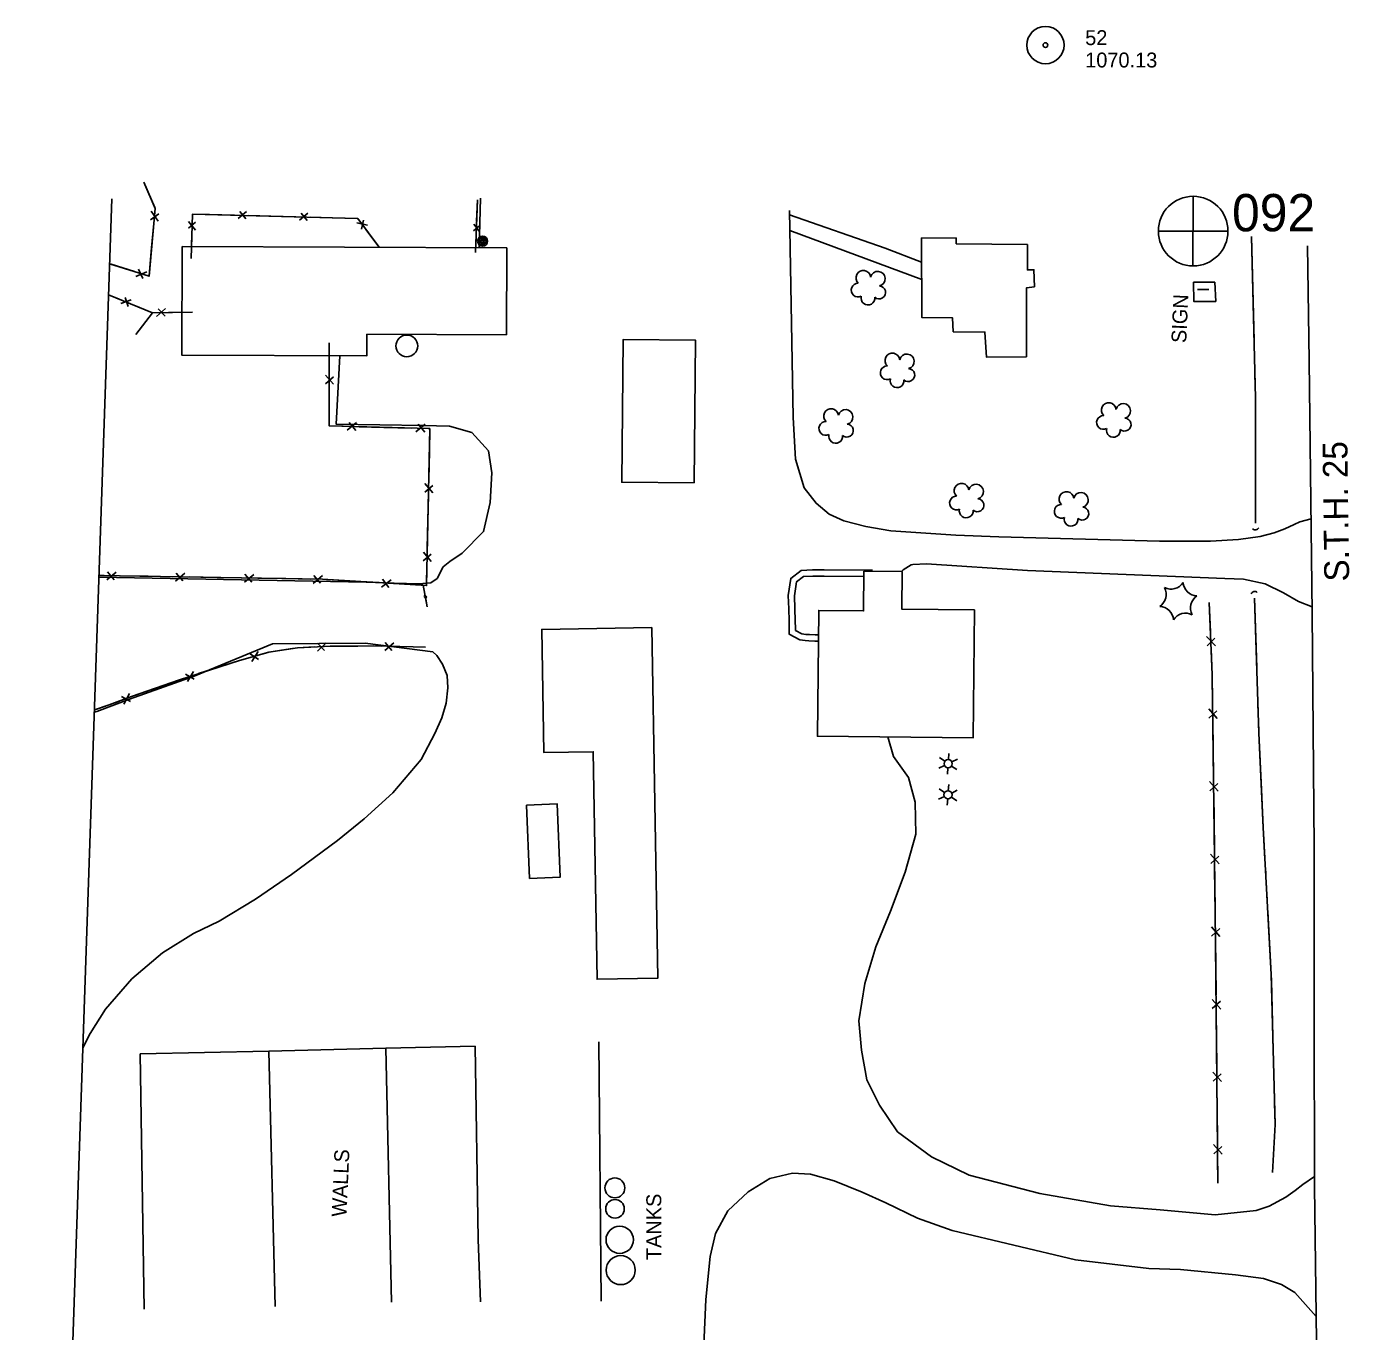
# Model space of a CAD drawing. Extents: x 296471 to 298892, y 33801 to 34997.
# Drawn here: x 297188 to 297720, y 34456 to 34981 of the extents above; entities that cross this region are included whole.
import ezdxf

# ---------------------------------------------------------------- set-up
doc = ezdxf.new("R2010")
doc.units = 0
for name, color, linetype in [('Level 11', 7, 'Continuous'), ('Level 12', 7, 'Continuous'), ('Level 14', 7, 'Continuous'), ('Level 15', 7, 'Continuous'), ('Level 17', 7, 'Continuous'), ('Level 18', 7, 'Continuous'), ('Level 19', 7, 'Continuous'), ('Level 4', 7, 'Continuous'), ('Level 6', 7, 'Continuous')]:
    doc.layers.add(name, color=color, linetype=linetype)

msp = doc.modelspace()

# ---------------------------------------------------------------- linework, layer by layer
at = {"layer": 'Level 11'}
msp.add_lwpolyline([(297712.34, 33851.57), (297711.29, 33914.53), (297711.16, 33974.94), (297710.5, 34028.32), (297710.34, 34091.16), (297709.89, 34145.17), (297708.94, 34222.49), (297708.52, 34278.1), (297707.52, 34365.88), (297707.09, 34441.48), (297706.15, 34514.1), (297705.99, 34583.52), (297706.04, 34650.6), (297705.21, 34744.77), (297704.07, 34846.29), (297703.4, 34892.56)], dxfattribs=at)
at = {"layer": 'Level 12'}
for points in [[(297380.91, 34856.8), (297381.05, 34891.74), (297250.46, 34892.28), (297250.28, 34848.61), (297324.72, 34848.3), (297324.76, 34857.03)], [(297456.56, 34797.17), (297427.36, 34797.44), (297427.89, 34854.88), (297457.09, 34854.61)], [(297569.36, 34746.06), (297568.79, 34694.57), (297506.1, 34695.28), (297506.67, 34745.9), (297524.67, 34745.7), (297524.85, 34761.67), (297540.2, 34761.5), (297540.03, 34746.39)], [(297439.45, 34738.98), (297395.18, 34738.23), (297396.02, 34688.7), (297415.9, 34689.03), (297417.45, 34597.46), (297441.84, 34597.88)], [(297389.02, 34667.51), (297401.39, 34668.02), (297402.59, 34638.56), (297390.23, 34638.05)]]:
    msp.add_lwpolyline(points, close=True, dxfattribs=at)
msp.add_lwpolyline([(297590.68, 34893.06), (297590.64, 34882.87), (297593.27, 34882.97), (297593.44, 34876.13), (297590.25, 34875.67), (297590.24, 34847.96), (297574.17, 34847.76), (297573.54, 34857.91), (297560.75, 34858), (297560.43, 34863.64), (297548.16, 34863.74), (297547.97, 34895.74), (297561.93, 34895.77), (297562.01, 34893.43), (297590.68, 34893.06)], dxfattribs=at)
for centre, radius in [((297340.83, 34852.31), 4.39), ((297424.59, 34513.52), 4), ((297424.64, 34505.1), 3.74), ((297426.52, 34492.66), 5.5), ((297426.94, 34480.44), 5.85)]:
    msp.add_circle(centre, radius, dxfattribs=at)
at = {"layer": 'Level 14'}
for p, q in [((297659.15, 34874.96), (297663.59, 34875.01)), ((297558.84, 34685.85), (297559.01, 34688.37)), ((297557.28, 34683.48), (297554.92, 34682.38)), ((297557.36, 34685.18), (297555.19, 34686.64)), ((297560.12, 34683.28), (297562.25, 34681.82)), ((297560.24, 34684.91), (297562.47, 34686.06)), ((297558.6, 34682.58), (297558.42, 34679.99)), ((297557.3, 34672.67), (297555.13, 34674.13)), ((297558.78, 34673.34), (297558.96, 34675.86)), ((297560.18, 34672.4), (297562.41, 34673.55)), ((297557.22, 34670.97), (297554.87, 34669.87)), ((297558.54, 34670.07), (297558.36, 34667.48)), ((297560.07, 34670.77), (297562.2, 34669.31))]:
    msp.add_line(p, q, dxfattribs=at)
for centre, radius in [((297371.36, 34894.47), 2.02), ((297371.34, 34894.47), 1.52), ((297371.38, 34894.48), 1.01), ((297371.37, 34894.48), 0.502), ((297558.74, 34684.21), 1.64), ((297558.68, 34671.7), 1.64)]:
    msp.add_circle(centre, radius, dxfattribs=at)
at = {"layer": 'Level 15'}
for p, q in [((297237.64, 34902.99), (297241, 34905.46)), ((297240.81, 34902.54), (297237.95, 34906.48)), ((297255.85, 34902.1), (297252.95, 34899.72)), ((297252.98, 34902.35), (297255.73, 34898.95)), ((297276.29, 34906.36), (297272.91, 34903.57)), ((297276.06, 34903.49), (297273.65, 34906.37)), ((297300.99, 34905.7), (297297.62, 34902.92)), ((297300.77, 34902.83), (297298.36, 34905.71)), ((297325.04, 34900.86), (297320.77, 34901.81)), ((297322.64, 34899.28), (297323.43, 34902.94)), ((297370.13, 34898.36), (297367.77, 34901.27)), ((297367.67, 34898.58), (297370.16, 34900.61)), ((297231.79, 34880.23), (297236.26, 34882.15)), ((297232.92, 34883.22), (297234.6, 34879.4)), ((297229.9, 34870.84), (297225.74, 34869.44)), ((297228.66, 34868.24), (297227.44, 34871.79)), ((297243.71, 34867.42), (297240.14, 34864.19)), ((297243.6, 34864.26), (297240.82, 34867.3)), ((297311.36, 34836.87), (297308.14, 34840.55)), ((297308.14, 34837.03), (297311.29, 34839.81)), ((297320.62, 34821.55), (297316.85, 34818.42)), ((297320.37, 34818.33), (297317.67, 34821.56)), ((297348.29, 34820.84), (297344.52, 34817.72)), ((297348.04, 34817.63), (297345.35, 34820.85)), ((297348.08, 34793.46), (297351.29, 34796.17)), ((297351.29, 34793.22), (297348.16, 34796.98)), ((297347.49, 34765.78), (297350.7, 34768.49)), ((297350.71, 34765.54), (297347.57, 34769.31)), ((297220.11, 34758.18), (297223.86, 34761.34)), ((297220.33, 34761.4), (297223.06, 34758.2)), ((297247.79, 34757.71), (297251.54, 34760.87)), ((297248.01, 34760.93), (297250.74, 34757.73)), ((297275.47, 34757.24), (297279.21, 34760.4)), ((297275.69, 34760.46), (297278.41, 34757.26)), ((297303.14, 34756.77), (297306.89, 34759.93)), ((297303.37, 34759.99), (297306.09, 34756.79)), ((297330.71, 34755.26), (297334.59, 34758.25)), ((297331.07, 34758.47), (297333.65, 34755.15)), ((297348.93, 34750.91), (297347.71, 34751.87)), ((297347.92, 34750.77), (297348.74, 34751.82)), ((297304.84, 34729.53), (297308.33, 34732.86)), ((297304.86, 34732.7), (297307.74, 34729.73)), ((297331.95, 34729.78), (297335.65, 34732.87)), ((297332.18, 34732.94), (297334.85, 34729.79)), ((297666.32, 34731.64), (297662.76, 34735.39)), ((297662.92, 34731.67), (297666.12, 34734.74)), ((297277.74, 34728.46), (297281.2, 34726.2)), ((297278.42, 34725.36), (297281.08, 34729.38)), ((297251.71, 34720.29), (297255.25, 34718.18)), ((297252.52, 34717.23), (297255.01, 34721.36)), ((297225.96, 34711.24), (297229.6, 34709.28)), ((297226.91, 34708.21), (297229.21, 34712.44)), ((297667.04, 34702.38), (297663.59, 34706.23)), ((297663.64, 34702.51), (297666.93, 34705.49)), ((297667.42, 34673.16), (297663.97, 34677.01)), ((297664.02, 34673.29), (297667.3, 34676.27)), ((297667.8, 34643.94), (297664.35, 34647.79)), ((297664.4, 34644.07), (297667.68, 34647.05)), ((297668.14, 34614.72), (297664.71, 34618.58)), ((297664.74, 34614.86), (297668.04, 34617.83)), ((297668.43, 34585.5), (297665, 34589.36)), ((297665.04, 34585.64), (297668.33, 34588.61)), ((297668.72, 34556.28), (297665.29, 34560.14)), ((297665.33, 34556.42), (297668.62, 34559.39)), ((297669.01, 34527.06), (297665.58, 34530.93)), ((297665.61, 34527.21), (297668.91, 34530.17))]:
    msp.add_line(p, q, dxfattribs=at)
for points in [[(297221.24, 34885.41), (297237.11, 34880.33), (297239.54, 34907.63), (297234.96, 34918.25)], [(297239.38, 34907.99), (297234.96, 34918.25)], [(297368.5, 34889.95), (297369.28, 34911.14)], [(297368.96, 34902.53), (297369.28, 34911.14)], [(297238.12, 34891.77), (297239, 34901.55)], [(297329.66, 34892.01), (297321.08, 34903.63), (297254.64, 34905.39), (297253.99, 34887.46)], [(297261.4, 34905.21), (297254.64, 34905.39), (297254.56, 34903.33)], [(297271.44, 34904.94), (297261.4, 34905.21)], [(297286.1, 34904.56), (297277.27, 34904.79)], [(297296.14, 34904.29), (297286.1, 34904.56)], [(297310.81, 34903.9), (297301.98, 34904.13)], [(297320.85, 34903.63), (297310.81, 34903.9)], [(297254.35, 34897.49), (297254.16, 34892.26)], [(297329.66, 34892.01), (297324.41, 34899.12)], [(297368.56, 34891.79), (297368.78, 34897.52)], [(297237.13, 34880.65), (297238.12, 34891.77)], [(297221.24, 34885.41), (297221.87, 34885.21)], [(297221.87, 34885.21), (297231.22, 34882.21)], [(297666.53, 34870.15), (297666.04, 34877.95), (297657.52, 34877.91)], [(297657.52, 34877.91), (297657.58, 34870.22), (297666.53, 34870.15)], [(297238.45, 34865.63), (297220.82, 34872.93)], [(297224.85, 34871.26), (297220.82, 34872.93)], [(297238.45, 34865.63), (297230.26, 34869.02)], [(297254.58, 34865.91), (297238.45, 34865.63), (297231.73, 34856.86)], [(297238.45, 34865.63), (297238.45, 34865.63), (297231.73, 34856.86)], [(297250.35, 34865.84), (297244.87, 34865.74)], [(297216.97, 34759.96), (297306.9, 34758.44), (297348.78, 34755.9), (297350.11, 34819.07), (297309.66, 34820.1), (297309.6, 34853.5)], [(297309.62, 34842.25), (297309.61, 34848.37)], [(297309.65, 34825.82), (297309.64, 34835.71)], [(297315.19, 34819.96), (297309.66, 34820.1), (297309.65, 34825.82)], [(297331.62, 34819.54), (297321.73, 34819.79)], [(297342.86, 34819.25), (297331.62, 34819.54)], [(297349.92, 34809.89), (297350.11, 34819.07), (297349.4, 34819.09)], [(297349.68, 34798.64), (297349.92, 34809.89)], [(297349.33, 34782.21), (297349.54, 34792.11)], [(297349.1, 34770.97), (297349.33, 34782.21)], [(297347.42, 34755.98), (297348.78, 34755.9), (297348.96, 34764.43)], [(297216.97, 34759.96), (297218.99, 34759.93)], [(297225.53, 34759.82), (297236.77, 34759.63)], [(297236.77, 34759.63), (297246.66, 34759.46)], [(297253.2, 34759.35), (297264.45, 34759.16)], [(297264.45, 34759.16), (297274.34, 34758.99)], [(297280.88, 34758.88), (297292.13, 34758.69)], [(297292.13, 34758.69), (297302.02, 34758.52)], [(297308.56, 34758.34), (297319.79, 34757.66)], [(297319.79, 34757.66), (297329.66, 34757.06)], [(297336.19, 34756.66), (297347.42, 34755.98)], [(297349.04, 34747.37), (297347.42, 34755.98)], [(297348.08, 34752.48), (297347.42, 34755.98)], [(297349.04, 34747.37), (297348.46, 34750.44)], [(297667.31, 34515.38), (297666.22, 34625.08), (297664.98, 34719.96), (297663.76, 34749.11)], [(297664.26, 34737.24), (297663.76, 34749.11)], [(297215.12, 34705.86), (297221.06, 34707.85), (297230.1, 34711.21), (297249.36, 34718), (297273.53, 34725.77), (297285.36, 34729.04), (297296.91, 34730.87), (297310.23, 34731.48), (297327.43, 34731.57), (297343.43, 34731.25), (297348.34, 34731.05)], [(297293.95, 34730.4), (297296.91, 34730.87), (297303.63, 34731.18)], [(297310.06, 34731.47), (297310.23, 34731.48), (297321.12, 34731.53)], [(297321.12, 34731.53), (297327.43, 34731.57), (297330.85, 34731.5)], [(297337.28, 34731.37), (297343.43, 34731.25), (297348.34, 34731.05)], [(297267.57, 34723.86), (297273.53, 34725.77), (297276.88, 34726.7)], [(297283.08, 34728.41), (297285.36, 34729.04), (297293.95, 34730.4)], [(297664.99, 34719.91), (297664.98, 34719.96), (297664.55, 34730.34)], [(297257.04, 34720.47), (297267.57, 34723.86)], [(297231.29, 34711.63), (297241.73, 34715.31)], [(297241.73, 34715.31), (297249.36, 34718), (297250.92, 34718.5)], [(297665.14, 34708.04), (297664.99, 34719.91)], [(297215.12, 34705.86), (297216.08, 34706.18)], [(297216.08, 34706.18), (297221.06, 34707.85), (297225.26, 34709.41)], [(297665.36, 34690.69), (297665.23, 34701.14)], [(297665.52, 34678.82), (297665.36, 34690.69)], [(297665.74, 34661.47), (297665.61, 34671.92)], [(297665.9, 34649.6), (297665.74, 34661.47)], [(297666.12, 34632.26), (297665.99, 34642.7)], [(297666.26, 34620.39), (297666.22, 34625.08), (297666.12, 34632.26)], [(297666.44, 34603.04), (297666.33, 34613.48)], [(297666.55, 34591.17), (297666.44, 34603.04)], [(297666.73, 34573.82), (297666.62, 34584.26)], [(297419.04, 34467.97), (297418.07, 34572.33)], [(297666.84, 34561.95), (297666.73, 34573.82)], [(297233.47, 34567.44), (297285.28, 34568.57), (297332.4, 34569.7), (297368.31, 34570.5)], [(297235.14, 34464.73), (297233.47, 34567.44)], [(297287.84, 34465.82), (297285.28, 34568.57)], [(297334.71, 34467.52), (297332.4, 34569.7)], [(297370.55, 34467.67), (297369.57, 34492.82), (297368.31, 34570.5)], [(297667.02, 34544.6), (297666.91, 34555.04)], [(297667.13, 34532.73), (297667.02, 34544.6)], [(297667.31, 34515.38), (297667.2, 34525.83)]]:
    msp.add_lwpolyline(points, dxfattribs=at)
for centre, radius, start, end in [((297682.37, 34779.88), 1.59, 224.6912, 330.9308), ((297682.13, 34751.9), 1.58, 49.445, 155.6846)]:
    msp.add_arc(centre, radius, start, end, dxfattribs=at)
at = {"layer": 'Level 17'}
for points in [[(297369.9, 34891.78), (297370.57, 34911.79)], [(297494.89, 34906.82), (297496.39, 34823.53), (297497.22, 34806.71), (297500.8, 34795.26), (297505.57, 34789), (297510.81, 34784.58), (297516.68, 34781.95), (297525.56, 34779.71), (297535.66, 34777.86), (297547.78, 34777.06), (297561.86, 34776.17), (297579.07, 34775.51), (297643.74, 34773.74), (297664.31, 34773.7), (297675.53, 34774.48), (297684.36, 34775.58), (297689.92, 34777.11), (297694.28, 34778.73), (297697.96, 34780.46), (297700.24, 34781.48), (297704.78, 34782.69)], [(297494.92, 34905.04), (297533.36, 34891.65), (297548.03, 34886.02)], [(297495.04, 34898.75), (297548.07, 34879)], [(297216.95, 34759.29), (297324.48, 34757.22), (297335.73, 34756.82), (297345.7, 34756.61), (297350.5, 34757.04), (297353.11, 34758.73), (297355.53, 34763.4), (297358.2, 34765.58), (297363.06, 34768.9), (297371.76, 34777.62), (297374.35, 34789.35), (297375.02, 34801.28), (297373.7, 34810.15), (297367.08, 34817.54), (297358.03, 34820.03), (297347.57, 34820.24), (297312.47, 34820.82), (297313.88, 34848.35)], [(297705.18, 34747.35), (297699.68, 34749.49), (297693.75, 34752.99), (297686.33, 34756.53), (297677.54, 34758.41), (297670.11, 34758.68), (297590.63, 34761.99), (297549.95, 34764.6), (297544.55, 34764.42), (297543.83, 34764.26), (297540.63, 34762.24), (297539.91, 34761.5)], [(297528.33, 34762.04), (297508.82, 34762.2), (297504.18, 34762.19), (297499.61, 34762), (297495.37, 34758.76), (297494.37, 34751.92), (297494.56, 34746.5), (297494.7, 34741.7), (297494.79, 34738.38), (297494.8, 34736.31), (297499.01, 34734.09), (297501.15, 34733.78), (297502.7, 34733.65), (297505.09, 34733.53), (297506.53, 34733.53)], [(297524.83, 34759.57), (297508.81, 34759.7), (297504.23, 34759.69), (297500.5, 34759.53), (297497.69, 34757.39), (297496.87, 34751.78), (297497.05, 34746.58), (297497.2, 34741.77), (297497.29, 34738.42), (297497.29, 34737.83), (297499.8, 34736.5), (297501.43, 34736.26), (297502.87, 34736.14), (297505.15, 34736.03), (297506.56, 34736.03)], [(297210.49, 34569.82), (297213.38, 34575.66), (297219.53, 34585.43), (297230.2, 34597.63), (297242.57, 34608.07), (297254.95, 34615.88), (297265.36, 34620.86), (297279.94, 34629.64), (297294.39, 34639.64), (297312.96, 34653.34), (297323.65, 34662), (297335.2, 34672.44), (297346.62, 34685.89), (297352.19, 34696.35), (297354.92, 34702.63), (297356.72, 34708.62), (297357.39, 34714.73), (297357.11, 34719.64), (297355.18, 34724.26), (297352.99, 34727.73), (297351.31, 34729.23), (297324.07, 34732.68), (297286.8, 34732.47), (297255.3, 34719.4), (297229.22, 34710.2), (297216.11, 34705.21), (297215.09, 34704.96)], [(297534.42, 34694.96), (297536.76, 34687.15), (297542.73, 34678.65), (297545.45, 34668.75), (297545.69, 34655.9), (297541.49, 34640.62), (297535.51, 34624.87), (297529.65, 34610.54), (297525.17, 34595.82), (297522.83, 34580.74), (297523.8, 34568.94), (297526, 34557.04), (297531.14, 34546.77), (297538.39, 34536.04), (297552.03, 34526.03), (297567.19, 34518.66), (297595.69, 34511.27), (297624.13, 34506.24), (297644.08, 34504.71), (297666.22, 34502.73), (297682.63, 34504.4), (297687.99, 34506.18), (297694.63, 34509.82), (297698.44, 34512.42), (297701.49, 34514.92), (297706.14, 34518.17)], [(297706.83, 34461.72), (297698.25, 34471.44), (297692.88, 34474.71), (297685.62, 34477.08), (297674.42, 34478.59), (297652.21, 34480.74), (297639.5, 34481.07), (297610.03, 34484.58), (297560.28, 34496.43), (297546.36, 34501.36), (297533.66, 34507.46), (297524.13, 34511.84), (297512.9, 34516.4), (297503.27, 34519.09), (297496.06, 34519.39), (297486.92, 34517.24), (297478.24, 34511.94), (297470.04, 34504.26), (297465.03, 34495.23), (297462.99, 34485.89), (297461.14, 34468.65), (297460.39, 34450.19)]]:
    msp.add_lwpolyline(points, dxfattribs=at)
at = {"layer": 'Level 18'}
for centre, radius, start, end in [((297524.58, 34879.72), 2.97, 5.9397, 227.1736), ((297530.42, 34879.35), 2.97, 283.5905, 166.5638), ((297522.5, 34874.76), 2.78, 88.9106, 296.6836), ((297530.95, 34873.85), 2.61, 228.2958, 86.2284), ((297526.44, 34871.58), 2.78, 165.5876, 6.5987), ((297536.28, 34846.45), 2.97, 5.9397, 227.1736), ((297542.12, 34846.09), 2.97, 283.5905, 166.5638), ((297534.21, 34841.49), 2.78, 88.9106, 296.6836), ((297542.65, 34840.59), 2.61, 228.2958, 86.2284), ((297538.15, 34838.32), 2.78, 165.5876, 6.5987), ((297511.59, 34824.08), 2.97, 5.9397, 227.1736), ((297517.43, 34823.71), 2.97, 283.5905, 166.5638), ((297623.35, 34826.49), 2.97, 5.9397, 227.1736), ((297629.19, 34826.13), 2.97, 283.5905, 166.5638), ((297509.51, 34819.12), 2.78, 88.9106, 296.6836), ((297621.27, 34821.53), 2.78, 88.9106, 296.6836), ((297629.72, 34820.63), 2.61, 228.2958, 86.2284), ((297513.46, 34815.95), 2.78, 165.5876, 6.5987), ((297517.96, 34818.22), 2.61, 228.2958, 86.2284), ((297625.22, 34818.36), 2.78, 165.5876, 6.5987), ((297564.13, 34794.05), 2.97, 5.9397, 227.1736), ((297569.97, 34793.69), 2.97, 283.5905, 166.5638), ((297562.06, 34789.09), 2.78, 88.9106, 296.6836), ((297570.5, 34788.19), 2.61, 228.2958, 86.2284), ((297606.34, 34790.7), 2.97, 5.9397, 227.1736), ((297612.18, 34790.33), 2.97, 283.5905, 166.5638), ((297566, 34785.92), 2.78, 165.5876, 6.5987), ((297604.27, 34785.74), 2.78, 88.9106, 296.6836), ((297612.71, 34784.83), 2.61, 228.2958, 86.2284), ((297608.21, 34782.57), 2.78, 165.5876, 6.5987), ((297640.77, 34752.33), 5.72, 302.7274, 28.4923), ((297648.43, 34760.15), 5.72, 242.7274, 328.4923), ((297659.02, 34757.43), 5.72, 182.7274, 268.4923), ((297643.72, 34741.79), 5.72, 2.7274, 88.4923), ((297661.97, 34746.89), 5.72, 122.7274, 208.4923), ((297654.32, 34739.07), 5.72, 62.7274, 148.4923)]:
    msp.add_arc(centre, radius, start, end, dxfattribs=at)
at = {"layer": 'Level 19'}
for points in [[(297680.8, 34896.4), (297682.45, 34831.24), (297682.48, 34780.97)], [(297680.8, 34896.4), (297681.86, 34854.56)], [(297682.01, 34848.79), (297682.08, 34845.9)], [(297682.22, 34840.13), (297682.3, 34837.25)], [(297682.44, 34831.47), (297682.45, 34831.24), (297682.45, 34828.59)], [(297682.45, 34822.82), (297682.48, 34780.97)], [(297682.08, 34750.81), (297683.74, 34696.52), (297685.53, 34658.52), (297688.78, 34599.43), (297690.32, 34538.98), (297689.33, 34519.72)], [(297682.08, 34750.81), (297682.94, 34722.88)], [(297683.05, 34719.02), (297683.11, 34717.1)], [(297683.23, 34713.24), (297683.29, 34711.32)], [(297683.41, 34707.46), (297683.47, 34705.54)], [(297683.59, 34701.68), (297683.74, 34696.52), (297684.82, 34673.76)], [(297684.82, 34673.76), (297685.53, 34658.52), (297686.23, 34645.85)], [(297686.44, 34642), (297686.55, 34640.08)], [(297686.76, 34636.23), (297686.86, 34634.3)], [(297687.08, 34630.46), (297687.18, 34628.53)], [(297687.39, 34624.68), (297688.78, 34599.43), (297688.85, 34596.77)], [(297688.85, 34596.77), (297689.56, 34568.83)], [(297689.66, 34564.98), (297689.71, 34563.05)], [(297689.81, 34559.2), (297689.86, 34557.27)], [(297689.95, 34553.42), (297690, 34551.49)], [(297690.1, 34547.64), (297690.32, 34538.98), (297689.33, 34519.72)]]:
    msp.add_lwpolyline(points, dxfattribs=at)
at = {"layer": 'Level 4'}
for p, q in [((297657.29, 34912.54), (297657.23, 34884.68)), ((297643.38, 34898.5), (297671.29, 34898.49))]:
    msp.add_line(p, q, dxfattribs=at)
msp.add_lwpolyline([(297187.76, 33864.29), (297191.46, 34011.67), (297222.13, 34911.46)], dxfattribs=at)
msp.add_circle((297657.34, 34898.51), 14, dxfattribs=at)
at = {"layer": 'Level 6'}
for radius in [7.5, 0.96]:
    msp.add_circle((297597.89, 34973.36), radius, dxfattribs=at)

# ---------------------------------------------------------------- texts
at = {"layer": 'Level 11'}
msp.add_text('S.T.H. 25', height=10, rotation=90.7627, dxfattribs=at).set_placement((297720.15, 34757.57))
at = {"layer": 'Level 12'}
msp.add_text('TANKS', height=6, rotation=90, dxfattribs=at).set_placement((297443.25, 34484.45))
at = {"layer": 'Level 14'}
msp.add_text('SIGN', height=6, rotation=87.5161, dxfattribs=at).set_placement((297654.55, 34853.38))
at = {"layer": 'Level 15'}
msp.add_text('WALLS', height=6, rotation=87.5161, dxfattribs=at).set_placement((297316.59, 34501.78))
at = {"layer": 'Level 4'}
msp.add_text('092', height=15, dxfattribs=at).set_placement((297672.99, 34898.44))
at = {"layer": 'Level 6'}
for s, p in [('52', (297613.89, 34973.36)), ('1070.13', (297613.89, 34964.36))]:
    msp.add_text(s, height=6, dxfattribs=at).set_placement(p)

doc.saveas('drawing.dxf')
